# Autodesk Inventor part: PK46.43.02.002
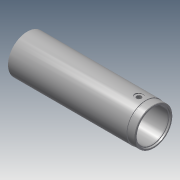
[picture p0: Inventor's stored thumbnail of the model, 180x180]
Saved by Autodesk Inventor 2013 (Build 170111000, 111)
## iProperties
Shininess: 64.0
Length Units: 11269
Angle Units: 11279
Time Units: 11290
Mass Units: 11283
Length Display Precision: 3
Angle Display Precision: 2
Compacted: True
Part Number: PK46.43.02.002
Document SubType Name: Modeling
Created: 2004-11
Material: Steel, High Strength Low Alloy
Designer: ELarisa
Manufacturer: Standard
Standards Organization: Custom
Density: 7.84 g/cm^3
Mass: 46748.1 g
Surface Area: 7315.57 cm^2
Volume: 5962.77 cm^3
Density: 0.0
Volumn: 0.0
Area: 0.0
PropertySet Name: Model Information
Control State: 0
Master: False
Checked Out: False
Checked Out Date: 2008-10-09
Last Check In Date: 2008-10-09
Author: ELarisa
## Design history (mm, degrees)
sketch "Эскиз1"
  geometry: L1 (-125.155, -154.996)-(-125.155, -72.496); L2 (-119.878, -57.996)-(477.845, -57.996); L3 (477.845, -57.996)-(477.845, -61.496); L4 (477.845, -61.496)-(482.845, -61.496); L5 (484.345, -59.996)-(515.845, -59.996); L6 (515.845, -59.996)-(517.845, -61.996); L7 (517.845, -61.996)-(517.845, -154.996); L8 (517.845, -154.996)-(-125.155, -154.996); L9 (-125.155, -74.996)-(504.845, -74.996); L10 (504.845, -74.996)-(509.845, -73.656); L11 (-125.155, -72.496)-(-119.878, -57.996); L12 (482.845, -61.496)-(484.345, -59.996); L13 (509.845, -73.656)-(509.845, -68.996); L14 (509.845, -68.996)-(517.845, -68.996)
  constraints: 28 end point, 6 parallel, 3 perpendicular, 2 point on line, 1 vertical
  dimensions: "d0" = 643 distance of L7.end L1.start; "d2" = 5 horizontal distance of L9.end L10.end; "d3" = 15 deg angle of L10 L9; "d4" = 20 deg angle of L11 L1; "d6" = 45 deg angle of L5 L12; "d7" = 5 distance of L3.end L4.end; "d8" = 40 distance between parallel lines of L3 L7; "d9" = 2 horizontal distance of L5.end L6.end; "d10" = 2 horizontal distance of L5.end L6.end; "d11" = 97 distance between parallel lines of L8 L2; "d12" = 95 distance between parallel lines of L8 L5; "d13" = 93.5 distance between parallel lines of L8 L4; "d14" = 80 distance between parallel lines of L8 L9; "d15" = 8 distance of L13.end L14.end; "d16" = 86 distance between parallel lines of L8 L14; "d17" = 82.5 distance of L1.start L1.end
revolve "Вращение1" sketch "Эскиз1" stored, may be unused: angle "d18" = 90 deg
node "РабПлоскость1"
sketch "Эскиз2"
  geometry: L1 (477.845, -251.996)-(477.845, -57.996) reference; L2 (-119.878, -57.996)-(477.845, -57.996) reference; 1 further point
  dimensions: "d20" = 97 distance from line of L2 point (442.845, -154.996); "d21" = 35 distance from line of L1 point (442.845, -154.996)
hole "Отверстие1" sketch "Эскиз2" diameter "d22" = 25; stored, may be unused: countersink angle "d26" = 82 deg, drill point angle "d28" = 118 deg; dims "d23" = 6, "d24" = 42, "d25" = 5, "d27" = 25
body "Solid1"
other parameters: "d19" = 97
